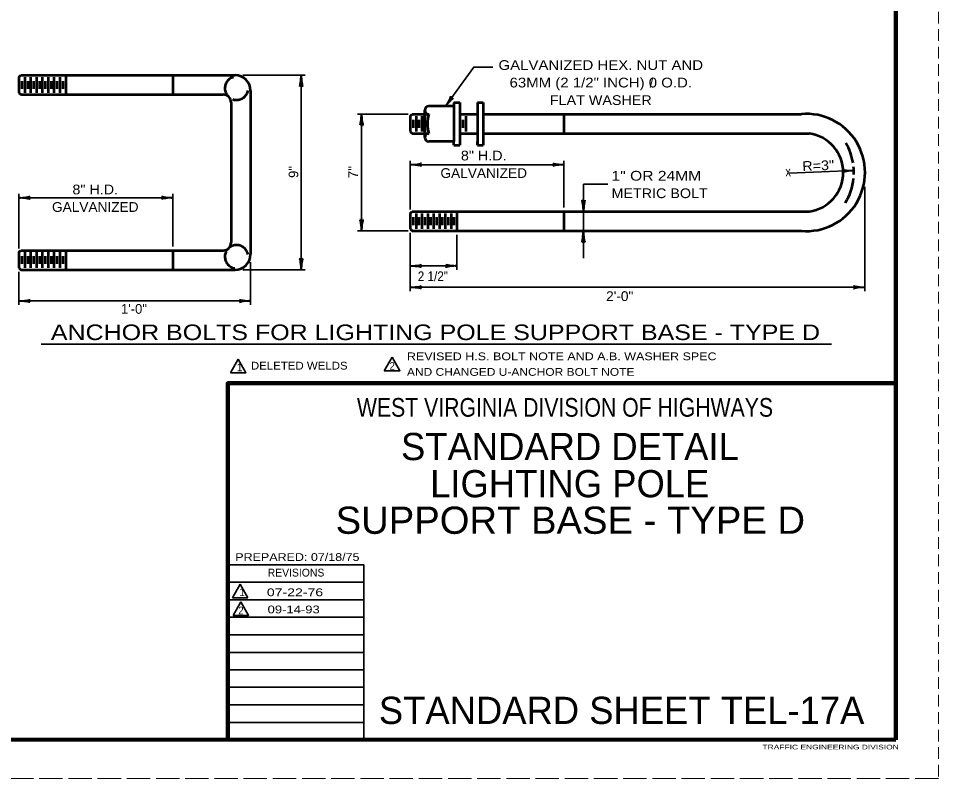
# Model space of a CAD drawing. Extents: x -1 to 679, y 0 to 440.
# Drawn here: x 442.6 to 679, y -0.3 to 195.1 of the extents above; entities that cross this region are included whole.
import ezdxf
from ezdxf.enums import TextEntityAlignment as Align

# ---------------------------------------------------------------- set-up
doc = ezdxf.new("R2010")
doc.units = 0
doc.linetypes.add('LONG_DASHED', pattern=[7.5, 6, -1.5])
doc.linetypes.add('MEDIUM_DASHED', pattern=[4.5, 3, -1.5])
doc.layers.add('1', color=7, linetype='Continuous', lineweight=35)
doc.layers.add('61', color=7, linetype='Continuous', lineweight=35)

msp = doc.modelspace()

# ---------------------------------------------------------------- linework, layer by layer
at = {"layer": '1', "linetype": 'MEDIUM_DASHED', "lineweight": 13}
msp.add_line((679.025, 439.78), (679.005, -0.24), dxfattribs=at)
at = {"layer": '1', "lineweight": 53}
for p, q in [((442.791, 179.963), (443.291, 180.463)), ((442.791, 179.963), (442.791, 175.963)), ((443.291, 180.463), (498.291, 180.463)), ((444.291, 179.963), (444.291, 175.963)), ((445.791, 179.963), (445.791, 175.963)), ((447.291, 179.963), (447.291, 175.963)), ((448.791, 179.963), (448.791, 175.963)), ((450.291, 179.963), (450.291, 175.963)), ((451.791, 179.963), (451.791, 175.963)), ((453.291, 179.963), (453.291, 175.963)), ((454.791, 180.463), (454.791, 175.463)), ((482.291, 180.463), (482.291, 175.463)), ((443.541, 178.963), (443.541, 176.963)), ((445.041, 178.963), (445.041, 176.963)), ((446.541, 178.963), (446.541, 176.963)), ((448.041, 178.963), (448.041, 176.963)), ((449.541, 178.963), (449.541, 176.963)), ((451.041, 178.963), (451.041, 176.963)), ((452.541, 178.963), (452.541, 176.963)), ((454.041, 178.963), (454.041, 176.963)), ((442.791, 175.963), (443.291, 175.463)), ((443.291, 175.463), (495.291, 175.463)), ((502.291, 176.463), (502.291, 134.463)), ((497.291, 173.463), (497.291, 137.463)), ((554.541, 173.463), (556.041, 173.463)), ((554.541, 173.463), (554.541, 172.463)), ((556.041, 173.463), (556.041, 162.463)), ((560.541, 173.463), (562.041, 173.463)), ((560.541, 173.463), (560.541, 172.463)), ((562.041, 173.463), (562.041, 162.463)), ((543.291, 169.963), (543.791, 170.463)), ((543.791, 170.463), (548.041, 170.463)), ((547.041, 164.463), (547.041, 171.463)), ((547.041, 171.463), (547.041, 164.463)), ((554.541, 172.463), (548.041, 172.463)), ((554.541, 172.463), (554.541, 163.463)), ((556.041, 170.463), (560.541, 170.463)), ((560.541, 172.463), (560.541, 162.463)), ((562.041, 170.463), (643.791, 170.463)), ((582.791, 170.463), (582.791, 165.463)), ((543.291, 169.963), (543.291, 165.963)), ((544.041, 168.963), (544.041, 166.963)), ((544.791, 169.963), (544.791, 165.963)), ((545.541, 168.963), (545.541, 166.963)), ((546.291, 169.963), (546.291, 165.963)), ((556.041, 169.963), (556.041, 165.963)), ((556.791, 168.963), (556.791, 166.963)), ((557.541, 169.963), (557.541, 165.963)), ((543.291, 165.963), (543.791, 165.463)), ((543.791, 165.463), (548.041, 165.463)), ((556.041, 165.463), (560.541, 165.463)), ((561.996, 165.463), (645.791, 165.463)), ((554.541, 163.463), (548.041, 163.463)), ((554.541, 162.463), (554.541, 163.463)), ((560.541, 162.463), (560.541, 163.463)), ((554.541, 162.463), (556.041, 162.463)), ((560.541, 162.463), (562.041, 162.463)), ((543.291, 144.963), (543.791, 145.463)), ((543.291, 144.963), (543.291, 140.963)), ((543.791, 145.463), (645.791, 145.463)), ((544.791, 144.963), (544.791, 140.963)), ((546.291, 144.963), (546.291, 140.963)), ((547.791, 144.963), (547.791, 140.963)), ((549.291, 144.963), (549.291, 140.963)), ((550.791, 144.963), (550.791, 140.963)), ((552.291, 144.963), (552.291, 140.963)), ((553.791, 144.963), (553.791, 140.963)), ((555.291, 145.463), (555.291, 140.463)), ((582.791, 145.463), (582.791, 140.463)), ((544.041, 143.963), (544.041, 141.963)), ((545.541, 143.963), (545.541, 141.963)), ((547.041, 143.963), (547.041, 141.963)), ((548.541, 143.963), (548.541, 141.963)), ((550.041, 143.963), (550.041, 141.963)), ((551.541, 143.963), (551.541, 141.963)), ((553.041, 143.963), (553.041, 141.963)), ((554.541, 143.963), (554.541, 141.963)), ((543.291, 140.963), (543.791, 140.463)), ((543.791, 140.463), (643.791, 140.463)), ((442.791, 134.963), (443.291, 135.463)), ((442.791, 134.963), (442.791, 130.963)), ((443.291, 135.463), (495.291, 135.463)), ((444.291, 134.963), (444.291, 130.963)), ((445.791, 134.963), (445.791, 130.963)), ((447.291, 134.963), (447.291, 130.963)), ((448.791, 134.963), (448.791, 130.963)), ((450.291, 134.963), (450.291, 130.963)), ((451.791, 134.963), (451.791, 130.963)), ((453.291, 134.963), (453.291, 130.963)), ((454.791, 135.463), (454.791, 130.463)), ((482.291, 135.463), (482.291, 130.463)), ((443.541, 133.963), (443.541, 131.963)), ((445.041, 133.963), (445.041, 131.963)), ((446.541, 133.963), (446.541, 131.963)), ((448.041, 133.963), (448.041, 131.963)), ((449.541, 133.963), (449.541, 131.963)), ((451.041, 133.963), (451.041, 131.963)), ((452.541, 133.963), (452.541, 131.963)), ((454.041, 133.963), (454.041, 131.963)), ((442.791, 130.963), (443.291, 130.463)), ((443.291, 130.463), (498.291, 130.463))]:
    msp.add_line(p, q, dxfattribs=at)
at = {"layer": '1'}
for p, q in [((500.291, 180.463), (516.291, 180.463)), ((515.291, 180.463), (515.291, 130.463)), ((542.791, 170.463), (529.791, 170.463)), ((530.791, 170.463), (530.791, 140.463)), ((543.291, 145.963), (543.291, 158.463)), ((582.791, 146.463), (582.791, 158.463)), ((543.291, 157.463), (582.791, 157.463)), ((657.237, 155.945), (640.66, 155.32)), ((587.791, 145.463), (587.791, 152.463)), ((587.791, 152.463), (594.031, 152.463)), ((660.078, 151.751), (660.078, 124.963)), ((442.791, 135.963), (442.791, 149.963)), ((442.791, 148.963), (482.291, 148.963)), ((482.291, 136.463), (482.291, 149.963)), ((542.791, 140.463), (529.791, 140.463)), ((543.291, 139.963), (543.291, 124.963)), ((555.291, 139.463), (555.291, 130.463)), ((502.291, 132.463), (502.291, 121.463)), ((500.291, 130.463), (516.291, 130.463)), ((555.291, 131.463), (543.291, 131.463)), ((442.791, 129.963), (442.791, 121.463)), ((543.291, 125.963), (660.078, 125.963)), ((442.791, 122.463), (502.291, 122.463)), ((448.488, 111.395), (651.506, 111.395)), ((499.104, 107.484), (497.104, 104.02)), ((538.642, 107.992), (536.642, 104.528)), ((531.405, 50.18), (496.425, 50.18)), ((499.621, 49.661), (497.621, 46.197)), ((499.621, 49.661), (501.621, 46.197)), ((531.405, 45.68), (496.425, 45.68)), ((501.621, 46.197), (497.621, 46.197)), ((499.776, 45.149), (497.776, 41.685)), ((531.405, 41.18), (496.425, 41.18)), ((531.405, 36.66), (496.425, 36.66)), ((531.405, 32.18), (496.425, 32.18)), ((531.405, 27.7), (496.425, 27.7)), ((531.405, 23.2), (496.425, 23.2)), ((531.405, 18.7), (496.425, 18.7)), ((531.405, 14.18), (496.425, 14.18))]:
    msp.add_line(p, q, dxfattribs=at)
for points in [[(552.374, 172.463), (559.625, 182.551), (564.516, 182.551)], [(587.791, 133.463), (587.791, 140.463), (587.791, 145.463)], [(499.104, 107.484), (501.104, 104.02), (497.104, 104.02)], [(538.642, 107.992), (540.642, 104.528), (536.642, 104.528)], [(531.405, 9.7), (531.405, 54.66), (496.425, 54.66)], [(499.776, 45.149), (501.776, 41.685), (497.776, 41.685)]]:
    msp.add_lwpolyline(points, dxfattribs=at)
at = {"layer": '1', "lineweight": 158}
msp.add_lwpolyline([(496.405, 9.74), (496.405, 101.32), (668.065, 101.32)], dxfattribs=at)
at = {"layer": '1', "linetype": 'LONG_DASHED', "lineweight": 53}
for centre, start, end in [((498.688, 177.104), 105.69018, 349.111), ((498.688, 133.819), 10.889, 261.06923)]:
    msp.add_arc(centre, 3, start, end, dxfattribs=at)
at = {"layer": '1', "lineweight": 53}
for centre, radius, start, end in [((498.291, 176.463), 4, 0, 90), ((495.291, 173.463), 2, 0, 90), ((548.041, 171.463), 1, 90, 180), ((548.041, 171.463), 1, 180, 270), ((558.315, 167.963), 10.574, 166.32376, 193.67624), ((645.078, 155.463), 15.055, 265.0952, 94.90479), ((548.041, 164.463), 1, 90, 180), ((644.453, 155.463), 10.089, 277.62006, 82.37994), ((548.041, 164.463), 1, 180, 270), ((642.19, 155.463), 15.055, 9.37052, 30.07893), ((642.19, 155.463), 15.055, 357.92796, 5.54536), ((642.19, 155.463), 15.055, 328.90929, 354.10244), ((495.291, 137.463), 2, 270, 0), ((498.291, 134.463), 4, 270, 0)]:
    msp.add_arc(centre, radius, start, end, dxfattribs=at)
at = {"layer": '1', "lineweight": 40}
for centre, major_axis, ratio, start_param, end_param in [((515.079, 179.343), (0.176, 1.756), 0.07063, 3.1407148, 5.41811), ((515.079, 179.343), (0.176, 1.756), 0.07063, 3.1407148, 5.41811), ((515.567, 179.372), (-0.156, 1.786), 0.122415, 0.8963533, 3.1415927), ((515.567, 179.372), (-0.156, 1.786), 0.122415, 0.8963533, 3.1415927), ((552.786, 173.511), (-0.916, -1.541), 0.122415, 0.8963533, 3.1415927), ((553.199, 173.25), (1.168, 1.324), 0.07063, 6.2823074, 8.5597026), ((530.579, 169.343), (0.176, 1.756), 0.07063, 3.1407148, 5.41811), ((530.579, 169.343), (0.176, 1.756), 0.07063, 3.1407148, 5.41811), ((531.067, 169.372), (-0.156, 1.786), 0.122415, 0.8963533, 3.1415927), ((531.067, 169.372), (-0.156, 1.786), 0.122415, 0.8963533, 3.1415927), ((544.382, 157.74), (-1.786, -0.156), 0.122415, 0.8963533, 3.1415927), ((544.382, 157.74), (-1.786, -0.156), 0.122415, 0.8963533, 3.1415927), ((544.412, 157.252), (-1.756, 0.176), 0.07063, 3.1407148, 5.41811), ((544.412, 157.252), (-1.756, 0.176), 0.07063, 3.1407148, 5.41811), ((581.7, 157.187), (1.786, 0.156), 0.122415, 0.8963533, 3.1415927), ((581.67, 157.675), (1.756, -0.176), 0.07063, 3.1407148, 5.41811), ((656.11, 156.114), (1.762, -0.109), 0.07063, 3.1407148, 5.41811), ((656.157, 155.628), (1.779, 0.223), 0.122415, 0.8963533, 3.1415927), ((443.882, 149.24), (-1.786, -0.156), 0.122415, 0.8963533, 3.1415927), ((443.882, 149.24), (-1.786, -0.156), 0.122415, 0.8963533, 3.1415927), ((443.912, 148.752), (-1.756, 0.176), 0.07063, 3.1407148, 5.41811), ((443.912, 148.752), (-1.756, 0.176), 0.07063, 3.1407148, 5.41811), ((481.2, 148.687), (1.786, 0.156), 0.122415, 0.8963533, 3.1415927), ((481.17, 149.175), (1.756, -0.176), 0.07063, 3.1407148, 5.41811), ((587.515, 146.555), (0.156, -1.786), 0.122415, 0.8963533, 3.1415927), ((587.515, 146.555), (0.156, -1.786), 0.122415, 0.8963533, 3.1415927), ((588.003, 146.584), (-0.176, -1.756), 0.07063, 3.1407148, 5.41811), ((588.003, 146.584), (-0.176, -1.756), 0.07063, 3.1407148, 5.41811), ((530.515, 141.555), (0.156, -1.786), 0.122415, 0.8963533, 3.1415927), ((531.003, 141.584), (-0.176, -1.756), 0.07063, 3.1407148, 5.41811), ((587.579, 139.343), (0.176, 1.756), 0.07063, 3.1407148, 5.41811), ((588.067, 139.372), (-0.156, 1.786), 0.122415, 0.8963533, 3.1415927), ((515.015, 131.555), (0.156, -1.786), 0.122415, 0.8963533, 3.1415927), ((515.015, 131.555), (0.156, -1.786), 0.122415, 0.8963533, 3.1415927), ((515.503, 131.584), (-0.176, -1.756), 0.07063, 3.1407148, 5.41811), ((515.503, 131.584), (-0.176, -1.756), 0.07063, 3.1407148, 5.41811), ((544.382, 131.74), (-1.786, -0.156), 0.122415, 0.8963533, 3.1415927), ((544.382, 131.74), (-1.786, -0.156), 0.122415, 0.8963533, 3.1415927), ((544.412, 131.252), (-1.756, 0.176), 0.07063, 3.1407148, 5.41811), ((544.412, 131.252), (-1.756, 0.176), 0.07063, 3.1407148, 5.41811), ((554.2, 131.187), (1.786, 0.156), 0.122415, 0.8963533, 3.1415927), ((554.17, 131.675), (1.756, -0.176), 0.07063, 3.1407148, 5.41811), ((544.382, 126.24), (-1.786, -0.156), 0.122415, 0.8963533, 3.1415927), ((544.382, 126.24), (-1.786, -0.156), 0.122415, 0.8963533, 3.1415927), ((544.412, 125.752), (-1.756, 0.176), 0.07063, 3.1407148, 5.41811), ((544.412, 125.752), (-1.756, 0.176), 0.07063, 3.1407148, 5.41811), ((658.987, 125.687), (1.786, 0.156), 0.122415, 0.8963533, 3.1415927), ((658.958, 126.175), (1.756, -0.176), 0.07063, 3.1407148, 5.41811), ((443.882, 122.74), (-1.786, -0.156), 0.122415, 0.8963533, 3.1415927), ((443.882, 122.74), (-1.786, -0.156), 0.122415, 0.8963533, 3.1415927), ((443.912, 122.252), (-1.756, 0.176), 0.07063, 3.1407148, 5.41811), ((443.912, 122.252), (-1.756, 0.176), 0.07063, 3.1407148, 5.41811), ((501.2, 122.187), (1.786, 0.156), 0.122415, 0.8963533, 3.1415927), ((501.17, 122.675), (1.756, -0.176), 0.07063, 3.1407148, 5.41811)]:
    msp.add_ellipse(centre, major_axis=major_axis, ratio=ratio, start_param=start_param, end_param=end_param, dxfattribs=at)
at = {"layer": '61', "lineweight": 158}
for p, q in [((668.045, 429.78), (668.065, 9.74)), ((668.065, 9.74), (29.005, 9.76))]:
    msp.add_line(p, q, dxfattribs=at)
at = {"layer": '61', "linetype": 'LONG_DASHED', "lineweight": 13}
msp.add_line((679.005, -0.24), (-1.055, -0.26), dxfattribs=at)

# ---------------------------------------------------------------- texts
at = {"layer": '1'}
for s, height, width, p in [('GALVANIZED HEX. NUT AND', 2.5, 1.15, (592.25, 181.813)), ('63MM (2 1/2" INCH) 0 O.D.', 2.5, 1.15, (592.25, 177.313)), ('FLAT WASHER', 2.5, 1.1, (592.25, 172.813)), ('8" H.D.', 2.5, 1.1, (562.181, 158.565)), ('GALVANIZED', 2.5, 1.05, (562.181, 154.065)), ('8" H.D.', 2.5, 1.1, (462.396, 149.849)), ('GALVANIZED', 2.5, 1.05, (462.396, 145.349)), ('WEST VIRGINIA DIVISION OF HIGHWAYS', 4.795, 0.85, (583.053, 92.72)), ('SUPPORT BASE - TYPE D', 6.993, 1.05, (584.429, 62.628)), ('07-22-76', 2, 1.35, (513.705, 46.6)), ('09-14-93', 2, 1.25, (513.355, 42.2))]:
    msp.add_text(s, height=height, dxfattribs=dict(at, width=width)).set_placement(p, align=Align.CENTER)
for s, height, p in [('/', 2.5, (604.829, 177.305)), ('1\'-0"', 2.5, (469.003, 119.165)), ('1', 2, (498.745, 104.401)), ('REVISIONS', 1.998, (506.685, 51.66)), ('1', 2, (499.371, 46.63)), ('STANDARD SHEET TEL-17A', 6.993, (535.245, 13.78))]:
    msp.add_text(s, height=height, dxfattribs=at).set_placement(p)
for s, rotation, width, p in [('R=3"', 2.158, 1.1, (644.063, 155.846)), ('7"', 90, 1.05, (529.859, 153.951)), ('x', 2.158, 0.85, (639.698, 154.441))]:
    msp.add_text(s, height=2.5, rotation=rotation, dxfattribs=dict(at, width=width)).set_placement(p)
msp.add_text('9"', height=2.5, rotation=90, dxfattribs=at).set_placement((514.558, 154.067))
for s, height, width, p in [('1" OR 24MM', 2.5, 1.2, (595.003, 153.376)), ('METRIC BOLT', 2.5, 1.1, (595.003, 148.876)), ('2 1/2"', 2.5, 0.9, (545.239, 127.549)), ('2\'-0"', 2.5, 1.05, (593.616, 122.444)), ('ANCHOR BOLTS FOR LIGHTING POLE SUPPORT BASE - TYPE D', 4, 1.2, (450.983, 112.407)), ('REVISED H.S. BOLT NOTE AND A.B. WASHER SPEC', 2, 1.2, (542.454, 107.227)), ('DELETED WELDS', 2, 1.1, (502.372, 104.828)), ('2', 2, 0.9, (538.011, 104.773)), ('AND CHANGED U-ANCHOR BOLT NOTE', 2, 1.15, (542.454, 103.227)), ('PREPARED: 07/18/75', 1.998, 1.2, (498.365, 55.66)), ('2', 2, 0.9, (499.144, 41.93)), ('TRAFFIC ENGINEERING DIVISION', 1.2, 1.35, (633.785, 7.24))]:
    msp.add_text(s, height=height, dxfattribs=dict(at, width=width)).set_placement(p)
for s, p in [('STANDARD DETAIL', (584.322, 81.56)), ('LIGHTING POLE', (584.275, 72.017))]:
    msp.add_text(s, height=6.993, dxfattribs=at).set_placement(p, align=Align.CENTER)

doc.saveas('drawing.dxf')
